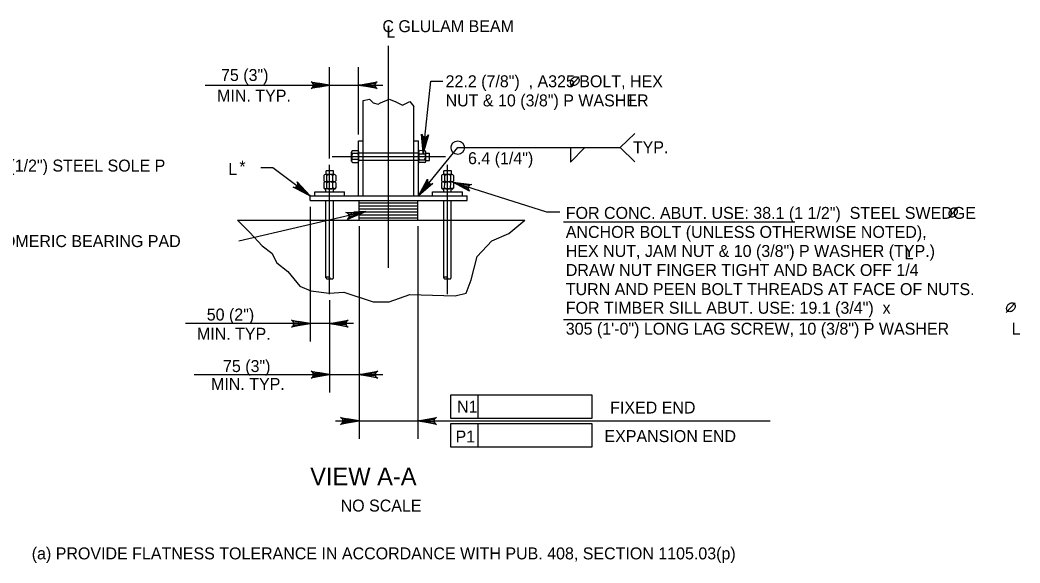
# Model space of a CAD drawing. Extents: x -13 to 81, y -176 to 0.
# Drawn here: x 11.59 to 21.63, y -170.32 to -164.87 of the extents above; entities that cross this region are included whole.
import ezdxf

# ---------------------------------------------------------------- set-up
doc = ezdxf.new("R2010")
doc.units = 0
for name, color, linetype in [('Level 3', 7, 'Continuous'), ('Level 4', 7, 'Continuous'), ('Level 52', 7, 'Continuous')]:
    doc.layers.add(name, color=color, linetype=linetype)

msp = doc.modelspace()

# ---------------------------------------------------------------- linework, layer by layer
at = {"layer": 'Level 3'}
for p, q in [((15.291, -167.362), (15.291, -165.132)), ((15.037, -166.638), (15.037, -165.681)), ((15.544, -166.638), (15.544, -165.742)), ((14.99, -166.087), (15.037, -166.087)), ((14.99, -166.638), (14.99, -166.087)), ((15.544, -166.087), (15.591, -166.087)), ((15.591, -166.638), (15.591, -166.087)), ((14.919, -166.29), (14.92, -166.199)), ((14.93, -166.184), (14.982, -166.184)), ((14.982, -166.215), (14.93, -166.215)), ((14.992, -166.29), (14.992, -166.199)), ((14.992, -166.207), (15.591, -166.207)), ((15.591, -166.291), (15.591, -166.2)), ((15.653, -166.186), (15.602, -166.185)), ((15.602, -166.216), (15.653, -166.217)), ((15.664, -166.292), (15.664, -166.201)), ((15.664, -166.21), (15.7, -166.21)), ((15.7, -166.284), (15.7, -166.21)), ((14.7, -167.624), (14.7, -166.327)), ((14.726, -166.244), (15.863, -166.244)), ((14.981, -166.275), (14.93, -166.275)), ((14.93, -166.304), (14.981, -166.304)), ((14.992, -166.282), (15.591, -166.282)), ((15.601, -166.276), (15.653, -166.277)), ((15.653, -166.305), (15.601, -166.305)), ((15.664, -166.284), (15.7, -166.284)), ((15.881, -167.624), (15.881, -166.327)), ((14.642, -166.435), (14.641, -166.487)), ((14.748, -166.425), (14.657, -166.425)), ((14.74, -166.389), (14.666, -166.389)), ((14.666, -166.425), (14.666, -166.389)), ((14.673, -166.487), (14.673, -166.435)), ((14.732, -166.487), (14.733, -166.436)), ((14.74, -166.425), (14.74, -166.389)), ((14.762, -166.436), (14.761, -166.487)), ((15.823, -166.435), (15.823, -166.487)), ((15.929, -166.425), (15.838, -166.425)), ((15.921, -166.389), (15.847, -166.389)), ((15.847, -166.425), (15.847, -166.389)), ((15.854, -166.487), (15.854, -166.435)), ((15.914, -166.487), (15.914, -166.436)), ((15.921, -166.425), (15.921, -166.389)), ((15.943, -166.436), (15.943, -166.487)), ((14.641, -166.508), (14.641, -166.559)), ((14.747, -166.498), (14.656, -166.498)), ((14.672, -166.56), (14.672, -166.508)), ((14.732, -166.56), (14.732, -166.508)), ((14.761, -166.508), (14.761, -166.56)), ((15.823, -166.508), (15.822, -166.559)), ((15.929, -166.498), (15.838, -166.498)), ((15.853, -166.56), (15.854, -166.508)), ((15.913, -166.56), (15.914, -166.508)), ((15.942, -166.508), (15.942, -166.56)), ((14.55, -166.638), (14.55, -166.599)), ((14.55, -166.599), (14.85, -166.599)), ((14.747, -166.57), (14.656, -166.57)), ((14.663, -166.599), (14.663, -166.57)), ((14.738, -166.599), (14.738, -166.57)), ((14.85, -166.638), (14.85, -166.599)), ((15.731, -166.599), (16.031, -166.599)), ((15.731, -166.638), (15.731, -166.599)), ((15.928, -166.57), (15.837, -166.57)), ((15.844, -166.599), (15.844, -166.57)), ((15.919, -166.599), (15.919, -166.57)), ((16.031, -166.638), (16.031, -166.599)), ((14.503, -166.685), (14.503, -166.638)), ((14.503, -166.638), (16.078, -166.638)), ((14.503, -166.685), (16.078, -166.685)), ((14.663, -166.882), (14.663, -166.685)), ((14.738, -166.882), (14.738, -166.685)), ((14.995, -166.882), (14.995, -166.685)), ((14.995, -166.71), (15.291, -166.71)), ((15.291, -166.71), (15.586, -166.71)), ((15.586, -166.882), (15.586, -166.685)), ((15.844, -166.882), (15.844, -166.685)), ((15.919, -166.882), (15.919, -166.685)), ((16.078, -166.685), (16.078, -166.638)), ((14.995, -166.74), (15.291, -166.74)), ((14.995, -166.769), (15.291, -166.769)), ((14.995, -166.799), (15.291, -166.799)), ((14.995, -166.828), (15.291, -166.828)), ((15.291, -166.74), (15.586, -166.74)), ((15.291, -166.769), (15.586, -166.769)), ((15.291, -166.799), (15.586, -166.799)), ((15.291, -166.828), (15.586, -166.828)), ((13.777, -166.882), (16.657, -166.882)), ((14.663, -167.463), (14.663, -166.882)), ((14.738, -167.463), (14.738, -166.882)), ((14.995, -166.858), (15.291, -166.858)), ((15.291, -166.858), (15.586, -166.858)), ((15.844, -167.463), (15.844, -166.882)), ((15.919, -167.463), (15.919, -166.882))]:
    msp.add_line(p, q, dxfattribs=at)
for points in [[(15.037, -165.681), (15.101, -165.669), (15.137, -165.706), (15.186, -165.718), (15.211, -165.706), (15.297, -165.669), (15.358, -165.693), (15.432, -165.73), (15.505, -165.693), (15.544, -165.742)], [(14.503, -166.638), (14.333, -166.553), (14.351, -166.554), (14.364, -166.549), (14.373, -166.54), (14.379, -166.529), (14.381, -166.514), (14.375, -166.498), (14.503, -166.638), (14.381, -166.514), (14.379, -166.529), (14.503, -166.638), (14.373, -166.54), (14.364, -166.549), (14.503, -166.638), (14.351, -166.554)], [(15.052, -166.799), (14.879, -166.875), (14.89, -166.862), (14.895, -166.849), (14.894, -166.836), (14.889, -166.824), (14.879, -166.814), (14.863, -166.807), (15.052, -166.799), (14.879, -166.814), (14.889, -166.824), (15.052, -166.799), (14.894, -166.836), (14.895, -166.849), (15.052, -166.799), (14.89, -166.862)], [(13.777, -166.882), (13.899, -167.005), (14.022, -167.139), (14.12, -167.213), (14.169, -167.311), (14.279, -167.397), (14.402, -167.544), (14.512, -167.593), (14.696, -167.617), (14.843, -167.605), (15.137, -167.703), (15.297, -167.703), (15.505, -167.629), (15.959, -167.642), (16.069, -167.617), (16.118, -167.482), (16.179, -167.249), (16.326, -167.09), (16.498, -167.017), (16.657, -166.882)]]:
    msp.add_lwpolyline(points, dxfattribs=at)
for centre, radius, start, end in [((14.967, -166.245), 0.0477, 140.8735, 218.7735), ((14.936, -166.199), 0.0167, 111.1104, 181.6506), ((14.936, -166.199), 0.0167, 181.6506, 248.5366), ((14.944, -166.245), 0.0477, 320.8735, 38.7735), ((14.976, -166.199), 0.0167, 357.9964, 68.5366), ((14.976, -166.199), 0.0167, 291.1104, 357.9964), ((15.608, -166.201), 0.0167, 111.1685, 181.7086), ((15.608, -166.201), 0.0167, 181.7086, 248.5946), ((15.639, -166.247), 0.0477, 140.9315, 218.8315), ((15.647, -166.201), 0.0167, 358.0545, 68.5946), ((15.647, -166.201), 0.0167, 291.1685, 358.0545), ((15.616, -166.246), 0.0477, 320.9315, 38.8315), ((14.934, -166.289), 0.0152, 107.2753, 252.3717), ((14.977, -166.289), 0.0152, 287.2753, 72.3717), ((15.606, -166.291), 0.0152, 107.3333, 252.4297), ((15.648, -166.291), 0.0152, 287.3333, 72.4297), ((14.657, -166.441), 0.0167, 88.0545, 158.5946), ((14.657, -166.441), 0.0167, 21.1685, 88.0545), ((14.703, -166.473), 0.0477, 50.9315, 128.8315), ((14.747, -166.44), 0.0152, 17.3333, 162.4297), ((15.838, -166.441), 0.0167, 88.0545, 158.5946), ((15.838, -166.441), 0.0167, 21.1685, 88.0545), ((15.884, -166.473), 0.0477, 50.9315, 128.8315), ((15.928, -166.44), 0.0152, 17.3333, 162.4297), ((14.657, -166.514), 0.0167, 88.0545, 158.5946), ((14.657, -166.481), 0.0167, 201.1685, 271.7086), ((14.657, -166.514), 0.0167, 21.1685, 88.0545), ((14.703, -166.45), 0.0477, 230.9315, 308.8315), ((14.702, -166.545), 0.0477, 50.9315, 128.8315), ((14.747, -166.482), 0.0152, 197.3333, 342.4297), ((14.747, -166.513), 0.0152, 17.3333, 162.4297), ((15.838, -166.481), 0.0167, 201.1685, 271.7086), ((15.838, -166.514), 0.0167, 88.0545, 158.5946), ((15.838, -166.481), 0.0167, 271.7086, 338.5946), ((15.838, -166.514), 0.0167, 21.1685, 88.0545), ((15.884, -166.45), 0.0477, 230.9315, 308.8315), ((15.884, -166.545), 0.0477, 50.9315, 128.8315), ((15.928, -166.482), 0.0152, 197.3333, 342.4297), ((15.928, -166.513), 0.0152, 17.3333, 162.4297), ((14.657, -166.553), 0.0167, 201.1685, 271.7086), ((14.657, -166.553), 0.0167, 271.7086, 338.5946), ((14.702, -166.522), 0.0477, 230.9315, 308.8315), ((14.747, -166.555), 0.0152, 197.3333, 342.4297), ((15.838, -166.553), 0.0167, 201.1685, 271.7086), ((15.838, -166.553), 0.0167, 271.7086, 338.5946), ((15.884, -166.522), 0.0477, 230.9315, 308.8315), ((15.928, -166.555), 0.0152, 197.3333, 342.4297), ((14.669, -167.463), 0.00549, 142.0693, 180), ((14.669, -167.463), 0.00549, 180, 217.9307), ((14.675, -167.468), 0.0133, 117.9903, 142.0693), ((14.675, -167.458), 0.0133, 217.9307, 242.0097), ((14.679, -167.475), 0.0221, 102.4157, 117.9903), ((14.679, -167.45), 0.0221, 242.0097, 257.5843), ((14.682, -167.488), 0.0347, 90, 102.4157), ((14.682, -167.438), 0.0347, 257.5843, 270), ((14.682, -167.488), 0.0347, 77.5843, 90), ((14.682, -167.438), 0.0347, 270, 282.4157), ((14.684, -167.475), 0.0221, 62.0097, 77.5843), ((14.684, -167.45), 0.0221, 282.4157, 297.9903), ((14.688, -167.468), 0.0133, 37.9307, 62.0097), ((14.688, -167.458), 0.0133, 297.9903, 322.0693), ((14.695, -167.463), 0.00549, 0, 37.9307), ((14.695, -167.463), 0.00549, 322.0693, 0), ((14.706, -167.463), 0.00549, 180, 217.9307), ((14.712, -167.458), 0.0133, 217.9307, 242.0097), ((14.716, -167.451), 0.0221, 242.0097, 257.5843), ((14.719, -167.438), 0.0347, 257.5843, 270), ((14.719, -167.438), 0.0347, 270, 282.4157), ((14.721, -167.451), 0.0221, 282.4157, 297.9903), ((14.725, -167.458), 0.0133, 297.9903, 322.0693), ((14.732, -167.463), 0.00549, 322.0693, 360), ((14.732, -167.463), 0.00549, 360, 1.757), ((15.85, -167.463), 0.00549, 142.0693, 180), ((15.85, -167.463), 0.00549, 180, 217.9307), ((15.856, -167.468), 0.0133, 117.9903, 142.0693), ((15.856, -167.458), 0.0133, 217.9307, 242.0097), ((15.86, -167.475), 0.0221, 102.4157, 117.9903), ((15.86, -167.45), 0.0221, 242.0097, 257.5843), ((15.863, -167.488), 0.0347, 90, 102.4157), ((15.863, -167.438), 0.0347, 257.5843, 270), ((15.863, -167.488), 0.0347, 77.5843, 90), ((15.863, -167.438), 0.0347, 270, 282.4157), ((15.865, -167.475), 0.0221, 62.0097, 77.5843), ((15.865, -167.45), 0.0221, 282.4157, 297.9903), ((15.869, -167.468), 0.0133, 37.9307, 62.0097), ((15.869, -167.458), 0.0133, 297.9903, 322.0693), ((15.876, -167.463), 0.00549, 0, 37.9307), ((15.876, -167.463), 0.00549, 322.0693, 0), ((15.887, -167.463), 0.00549, 180, 217.9307), ((15.893, -167.458), 0.0133, 217.9307, 242.0097), ((15.897, -167.451), 0.0221, 242.0097, 257.5843), ((15.9, -167.438), 0.0347, 257.5843, 270), ((15.9, -167.438), 0.0347, 270, 282.4157), ((15.902, -167.451), 0.0221, 282.4157, 297.9903), ((15.906, -167.458), 0.0133, 297.9903, 322.0693), ((15.913, -167.463), 0.00549, 322.0693, 360), ((15.913, -167.463), 0.00549, 360, 1.757)]:
    msp.add_arc(centre, radius, start, end, dxfattribs=at)
at = {"layer": 'Level 4'}
for p, q in [((14.7, -166.264), (14.7, -165.348)), ((14.99, -166.024), (14.99, -165.348)), ((13.451, -165.528), (15.235, -165.528)), ((15.637, -166.21), (15.715, -165.488)), ((15.715, -165.488), (15.835, -165.488)), ((17.113, -165.541), (17.203, -165.443)), ((17.616, -166.155), (17.761, -166.012)), ((15.591, -166.638), (15.985, -166.155)), ((15.985, -166.155), (17.616, -166.155)), ((17.117, -166.155), (17.117, -166.302)), ((17.117, -166.302), (17.259, -166.155)), ((17.616, -166.155), (17.761, -166.299)), ((14.129, -166.356), (14.009, -166.356)), ((14.503, -166.638), (14.129, -166.356)), ((15.052, -166.799), (13.789, -167.093)), ((14.503, -166.748), (14.503, -168.101)), ((20.909, -166.858), (20.999, -166.76)), ((17.047, -166.9), (19.367, -166.9)), ((14.995, -166.944), (14.995, -169.077)), ((15.586, -166.944), (15.586, -169.077)), ((14.7, -167.687), (14.7, -168.612)), ((21.488, -167.81), (21.578, -167.712)), ((14.939, -167.921), (13.253, -167.921)), ((17.047, -167.878), (20.125, -167.878)), ((13.34, -168.432), (15.235, -168.432)), ((15.917, -168.636), (16.191, -168.636)), ((15.917, -168.873), (15.917, -168.636)), ((16.191, -168.873), (16.191, -168.636)), ((16.191, -168.636), (17.329, -168.636)), ((17.329, -168.636), (17.329, -168.873)), ((14.757, -168.897), (19.12, -168.897)), ((17.329, -168.873), (15.917, -168.873)), ((15.917, -168.924), (16.191, -168.924)), ((15.917, -169.16), (15.917, -168.924)), ((16.191, -169.16), (16.191, -168.924)), ((16.191, -168.924), (17.329, -168.924)), ((17.329, -168.924), (17.329, -169.16)), ((17.329, -169.16), (15.917, -169.16))]:
    msp.add_line(p, q, dxfattribs=at)
for points in [[(14.7, -165.528), (14.514, -165.563), (14.528, -165.553), (14.535, -165.54), (14.538, -165.528), (14.535, -165.515), (14.528, -165.503), (14.514, -165.493), (14.7, -165.528), (14.528, -165.503), (14.535, -165.515), (14.7, -165.528), (14.538, -165.528), (14.535, -165.54), (14.7, -165.528), (14.528, -165.553)], [(14.99, -165.528), (15.176, -165.493), (15.162, -165.503), (15.155, -165.515), (15.153, -165.528), (15.155, -165.54), (15.162, -165.553), (15.176, -165.563), (14.99, -165.528), (15.162, -165.553), (15.155, -165.54), (14.99, -165.528), (15.153, -165.528), (15.155, -165.515), (14.99, -165.528), (15.162, -165.503)], [(15.637, -166.21), (15.622, -166.021), (15.63, -166.036), (15.642, -166.045), (15.654, -166.048), (15.667, -166.047), (15.68, -166.041), (15.692, -166.028), (15.637, -166.21), (15.68, -166.041), (15.667, -166.047), (15.637, -166.21), (15.654, -166.048), (15.642, -166.045), (15.637, -166.21), (15.63, -166.036)], [(15.591, -166.638), (15.682, -166.471), (15.681, -166.489), (15.686, -166.502), (15.694, -166.512), (15.705, -166.518), (15.719, -166.52), (15.736, -166.516), (15.591, -166.638), (15.719, -166.52), (15.705, -166.518), (15.591, -166.638), (15.694, -166.512), (15.686, -166.502), (15.591, -166.638), (15.681, -166.489)], [(14.503, -167.921), (14.317, -167.956), (14.331, -167.946), (14.338, -167.934), (14.341, -167.921), (14.338, -167.909), (14.331, -167.896), (14.317, -167.886), (14.503, -167.921), (14.331, -167.896), (14.338, -167.909), (14.503, -167.921), (14.341, -167.921), (14.338, -167.934), (14.503, -167.921), (14.331, -167.946)], [(14.7, -167.921), (14.886, -167.886), (14.872, -167.896), (14.865, -167.909), (14.863, -167.921), (14.865, -167.934), (14.872, -167.946), (14.886, -167.956), (14.7, -167.921), (14.872, -167.946), (14.865, -167.934), (14.7, -167.921), (14.863, -167.921), (14.865, -167.909), (14.7, -167.921), (14.872, -167.896)], [(14.7, -168.432), (14.514, -168.467), (14.528, -168.457), (14.535, -168.444), (14.538, -168.432), (14.535, -168.419), (14.528, -168.407), (14.514, -168.397), (14.7, -168.432), (14.528, -168.407), (14.535, -168.419), (14.7, -168.432), (14.538, -168.432), (14.535, -168.444), (14.7, -168.432), (14.528, -168.457)], [(14.995, -168.432), (15.182, -168.397), (15.167, -168.407), (15.16, -168.419), (15.158, -168.432), (15.16, -168.444), (15.167, -168.457), (15.182, -168.467), (14.995, -168.432), (15.167, -168.457), (15.16, -168.444), (14.995, -168.432), (15.158, -168.432), (15.16, -168.419), (14.995, -168.432), (15.167, -168.407)], [(14.995, -168.897), (14.809, -168.932), (14.823, -168.922), (14.831, -168.909), (14.833, -168.897), (14.831, -168.884), (14.823, -168.872), (14.809, -168.862), (14.995, -168.897), (14.823, -168.872), (14.831, -168.884), (14.995, -168.897), (14.833, -168.897), (14.831, -168.909), (14.995, -168.897), (14.823, -168.922)], [(15.586, -168.897), (15.772, -168.862), (15.758, -168.872), (15.75, -168.884), (15.748, -168.897), (15.75, -168.909), (15.758, -168.922), (15.772, -168.932), (15.586, -168.897), (15.758, -168.922), (15.75, -168.909), (15.586, -168.897), (15.748, -168.897), (15.75, -168.884), (15.586, -168.897), (15.758, -168.872)]]:
    msp.add_lwpolyline(points, dxfattribs=at)
for points in [[(14.58, -165.508), (14.58, -165.548), (14.7, -165.528)], [(15.11, -165.508), (15.11, -165.548), (14.99, -165.528)], [(15.632, -166.068), (15.672, -166.072), (15.639, -166.189)], [(15.682, -166.558), (15.651, -166.532), (15.591, -166.638)], [(14.419, -166.55), (14.395, -166.582), (14.503, -166.638)], [(14.942, -166.804), (14.951, -166.843), (15.063, -166.797)], [(14.383, -167.901), (14.383, -167.941), (14.503, -167.921)], [(14.82, -167.901), (14.82, -167.941), (14.7, -167.921)], [(14.58, -168.412), (14.58, -168.452), (14.7, -168.432)], [(15.115, -168.412), (15.115, -168.452), (14.995, -168.432)], [(14.875, -168.877), (14.875, -168.917), (14.995, -168.897)], [(15.706, -168.877), (15.706, -168.917), (15.586, -168.897)]]:
    msp.add_lwpolyline(points, close=True, dxfattribs=at)
msp.add_circle((15.985, -166.155), 0.0675, dxfattribs=at)
msp.add_arc((14.706, -167.463), 0.00549, 180, 182.0078, dxfattribs=at)
for points in [[(17.194, -165.452), (17.186, -165.447), (17.179, -165.445), (17.171, -165.444), (17.166, -165.444), (17.157, -165.446), (17.149, -165.45), (17.144, -165.453), (17.133, -165.461), (17.125, -165.472), (17.12, -165.482), (17.117, -165.491), (17.116, -165.5), (17.117, -165.507), (17.12, -165.518), (17.124, -165.523), (17.132, -165.529), (17.143, -165.532), (17.157, -165.532), (17.174, -165.524), (17.186, -165.514), (17.195, -165.501), (17.201, -165.488), (17.203, -165.473), (17.2, -165.463), (17.194, -165.452)], [(20.989, -166.77), (20.982, -166.764), (20.975, -166.762), (20.967, -166.762), (20.962, -166.762), (20.953, -166.763), (20.945, -166.767), (20.94, -166.77), (20.929, -166.779), (20.921, -166.79), (20.916, -166.8), (20.913, -166.809), (20.912, -166.817), (20.913, -166.825), (20.916, -166.835), (20.92, -166.841), (20.928, -166.847), (20.939, -166.85), (20.953, -166.849), (20.97, -166.841), (20.982, -166.831), (20.991, -166.818), (20.997, -166.805), (20.999, -166.79), (20.996, -166.781), (20.99, -166.77)], [(21.569, -167.721), (21.561, -167.716), (21.554, -167.714), (21.546, -167.713), (21.541, -167.713), (21.532, -167.715), (21.524, -167.719), (21.519, -167.722), (21.508, -167.73), (21.5, -167.741), (21.495, -167.751), (21.492, -167.76), (21.491, -167.769), (21.492, -167.776), (21.495, -167.787), (21.499, -167.792), (21.507, -167.798), (21.518, -167.801), (21.532, -167.801), (21.549, -167.793), (21.561, -167.782), (21.57, -167.77), (21.576, -167.756), (21.578, -167.742), (21.575, -167.732), (21.569, -167.721)]]:
    msp.add_spline(points, degree=3, dxfattribs=at)
at = {"layer": 'Level 52'}
for points in [[(15.937, -166.501), (16.876, -166.8), (17.008, -166.8)], [(15.937, -166.501), (16.125, -166.524), (16.109, -166.529), (16.098, -166.539), (16.092, -166.55), (16.09, -166.563), (16.094, -166.577), (16.104, -166.591), (15.937, -166.501), (16.094, -166.577), (16.09, -166.563), (15.937, -166.501), (16.092, -166.55), (16.098, -166.539), (15.937, -166.501), (16.109, -166.529)]]:
    msp.add_lwpolyline(points, dxfattribs=at)

# ---------------------------------------------------------------- texts
at = {"layer": 'Level 4'}
for s, height, p in [('C GLULAM BEAM', 0.12, (15.229, -164.996)), ('L', 0.12, (15.269, -165.052)), ('75 (3")', 0.12, (13.61, -165.486)), ('22.2 (7/8")  , A325 BOLT, HEX', 0.12, (15.863, -165.549)), ('MIN. TYP.', 0.12, (13.571, -165.693)), ('NUT & 10 (3/8") P WASHER', 0.12, (15.863, -165.741)), ('L', 0.12, (17.698, -165.741)), ('TYP.', 0.12, (17.742, -166.211)), ('6.4 (1/4")', 0.12, (16.088, -166.321)), ('12 (1/2") STEEL SOLE P', 0.12, (11.264, -166.395)), ('L', 0.12, (13.682, -166.428)), ('*', 0.12, (13.794, -166.405)), ('FOR CONC. ABUT. USE: 38.1 (1 1/2")  STEEL SWEDGE', 0.12, (17.069, -166.87)), ('ANCHOR BOLT (UNLESS OTHERWISE NOTED), ', 0.12, (17.069, -167.061)), ('ELASTOMERIC BEARING PAD', 0.12, (10.914, -167.153)), ('HEX NUT, JAM NUT & 10 (3/8") P WASHER (TYP.)', 0.12, (17.069, -167.252)), ('L', 0.12, (20.467, -167.277)), ('DRAW NUT FINGER TIGHT AND BACK OFF 1/4', 0.12, (17.069, -167.443)), ('TURN AND PEEN BOLT THREADS AT FACE OF NUTS.', 0.12, (17.069, -167.635)), ('FOR TIMBER SILL ABUT. USE: 19.1 (3/4")  x ', 0.12, (17.069, -167.822)), ('50 (2")', 0.12, (13.467, -167.89)), ('305 (1\'-0") LONG LAG SCREW, 10 (3/8") P WASHER', 0.12, (17.069, -168.032)), ('L', 0.12, (21.542, -168.032)), ('MIN. TYP.', 0.12, (13.368, -168.083)), ('75 (3")', 0.12, (13.63, -168.407)), ('MIN. TYP.', 0.12, (13.51, -168.587)), ('N1', 0.12, (15.979, -168.815)), ('FIXED END', 0.12, (17.514, -168.823)), ('P1', 0.12, (15.963, -169.114)), ('EXPANSION END', 0.12, (17.457, -169.11)), ('VIEW A-A', 0.1772, (14.505, -169.543)), ('NO SCALE', 0.12, (14.81, -169.807)), ('(a) PROVIDE FLATNESS TOLERANCE IN ACCORDANCE WITH PUB. 408, SECTION 1105.03(p)', 0.12, (11.711, -170.287))]:
    msp.add_text(s, height=height, dxfattribs=at).set_placement(p)

doc.saveas('drawing.dxf')
